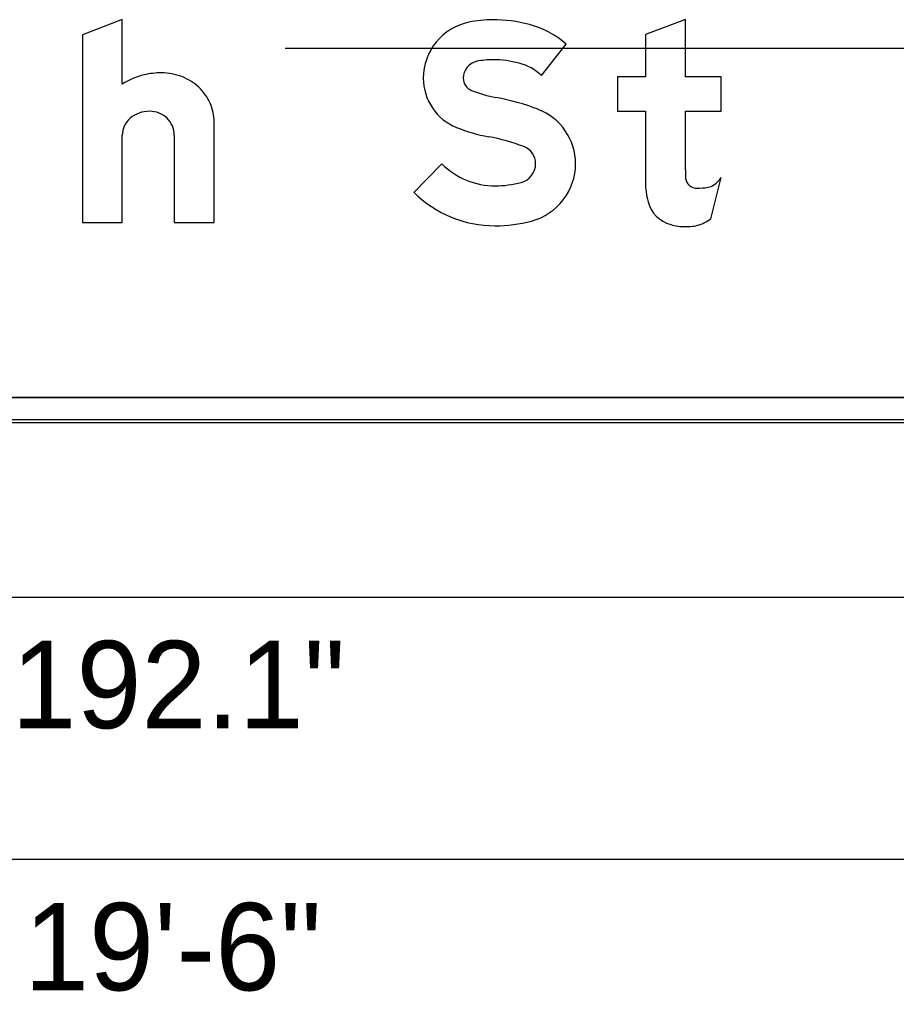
# Model space of a CAD drawing. Extents: x 2149934 to 2150188, y 145114 to 145238.
# Drawn here: x 2150097.15 to 2150103.01, y 145194.64 to 145201.13 of the extents above; entities that cross this region are included whole.
import ezdxf

# ---------------------------------------------------------------- set-up
doc = ezdxf.new("R2010")
doc.units = 0
for name, color, linetype in [('GSBWFILL', 7, 'Continuous'), ('GSCOLORFILL', 7, 'Continuous'), ('GSDIMS', 7, 'Continuous'), ('GSOUTLINE', 7, 'Continuous'), ('NON-PLOT', 7, 'Continuous')]:
    doc.layers.add(name, color=color, linetype=linetype)

msp = doc.modelspace()

# ---------------------------------------------------------------- linework, layer by layer
at = {"layer": 'GSBWFILL'}
for p, q in [((2150101.7691, 145199.8029), (2150101.8393, 145200.0789)), ((2150107.2786, 145198.6114), (2150088.7803, 145198.6114)), ((2150088.7803, 145198.4447), (2150107.2786, 145198.4447))]:
    msp.add_line(p, q, dxfattribs=at)
for points in [[(2150097.8393, 145200.7033), (2150097.8393, 145201.1347), (2150097.5726, 145201.0318), (2150097.5726, 145199.7781), (2150097.8393, 145199.7781), (2150097.8393, 145200.3629)], [(2150101.5993, 145200.1314), (2150101.5993, 145200.5214), (2150101.8393, 145200.5214), (2150101.8393, 145200.7514), (2150101.5993, 145200.7514), (2150101.5993, 145201.1347), (2150101.3326, 145201.0336), (2150101.3326, 145200.7514), (2150101.146, 145200.7514), (2150101.146, 145200.5214), (2150101.3326, 145200.5214), (2150101.3326, 145200.0508)], [(2150100.6394, 145200.7595), (2150100.8043, 145200.9699)], [(2150098.186, 145200.3629), (2150098.186, 145199.7781), (2150098.4526, 145199.7781), (2150098.4526, 145200.4506)], [(2150099.9737, 145200.1699), (2150099.786, 145199.9805)]]:
    msp.add_lwpolyline(points, dxfattribs=at)
for centre, major_axis, ratio, start_param, end_param in [((2150100.3126, 145200.347), (0, 0.7855), 0.999996, 0, 0.202758), ((2150100.3126, 145200.1692), (0, 0.9632), 0.999996, 6.026234, 6.283185), ((2150100.2313, 145200.7422), (0, 0.382), 0.999996, 0.202758, 1.570796), ((2150100.402, 145200.5094), (0, 0.6115), 0.999996, 5.565152, 6.026234), ((2150100.3126, 145200.347), (0, 0.5188), 0.999996, 0, 0.202758), ((2150100.3126, 145200.1692), (0, 0.6965), 0.999996, 6.026234, 6.283185), ((2150100.2313, 145200.7422), (0, 0.1153), 0.999996, 0.202758, 1.570796), ((2150100.402, 145200.5094), (0, 0.3448), 0.999996, 5.523837, 6.026234), ((2150098.0972, 145200.2983), (0, 0.4802), 0.999993, 0.235088, 0.567132), ((2150098.1018, 145200.2447), (0, 0.5334), 0.999993, 0, 0.219986), ((2150098.1018, 145200.4027), (0, 0.3754), 0.999993, 5.914285, 6.283185), ((2150098.1108, 145200.4261), (0, 0.3503), 0.999993, 5.532258, 5.914285), ((2150100.2032, 145200.7422), (0, 0.3538), 0.999996, 1.570796, 2.761249), ((2150100.2032, 145200.7422), (0, 0.0872), 0.999996, 1.570796, 2.761249), ((2150098.1248, 145200.441), (0, 0.3299), 0.999993, 5.130076, 5.532258), ((2150100.4938, 145201.469), (0, 0.8699), 0.999996, 2.761249, 2.95744), ((2150100.0373, 145199.018), (0, 1.6233), 0.999996, 5.918637, 6.099033), ((2150098.1465, 145200.4506), (0, 0.3062), 0.999993, 4.712389, 5.130076), ((2150097.9995, 145200.3527), (0, 0.1625), 0.999993, 0.715718, 1.126231), ((2150098.0133, 145200.3369), (0, 0.1835), 0.999993, 0.345704, 0.715718), ((2150098.0222, 145200.312), (0, 0.2099), 0.999993, 0, 0.345704), ((2150098.0222, 145200.3535), (0, 0.1684), 0.999993, 5.900624, 6.283185), ((2150098.0241, 145200.3581), (0, 0.1635), 0.999993, 5.51227, 5.900624), ((2150098.0269, 145200.361), (0, 0.1594), 0.999993, 5.115435, 5.51227), ((2150100.4775, 145200.1716), (0, 0.3885), 0.999996, 4.712389, 5.918637), ((2150097.9782, 145200.3629), (0, 0.1389), 0.999993, 1.126231, 1.570796), ((2150098.0313, 145200.3629), (0, 0.1546), 0.999993, 4.712389, 5.115435), ((2150100.4938, 145201.469), (0, 1.1366), 0.999996, 2.761249, 2.95744), ((2150100.0373, 145199.018), (0, 1.3566), 0.999996, 5.918637, 6.099033), ((2150100.4775, 145200.1716), (0, 0.1218), 0.999996, 4.712389, 5.918637), ((2150100.3288, 145200.5282), (0, 0.5044), 0.999996, 2.360607, 3.141593), ((2150100.4698, 145200.1716), (0, 0.1295), 0.999996, 3.401517, 4.712389), ((2150100.4698, 145200.1716), (0, 0.3961), 0.999996, 3.401517, 4.712389), ((2150103.2686, 145200.1314), (0, 1.6693), 0.999994, 1.570796, 1.606005), ((2150100.3288, 145200.702), (0, 0.6782), 0.999996, 3.141593, 3.401517), ((2150101.85, 145200.0508), (0, 0.5174), 0.999994, 1.570796, 1.830698), ((2150101.6759, 145200.0856), (0, 0.0767), 0.999994, 1.74085, 2.407828), ((2150101.6783, 145200.0883), (0, 0.0803), 0.999994, 2.407828, 3.141593), ((2150101.7324, 145200.1126), (0, 0.1), 0.999994, 3.310762, 3.756278), ((2150101.6638, 145200.2098), (0, 0.2189), 0.999994, 3.756278, 4.071638), ((2150100.3288, 145200.5282), (0, 0.7711), 0.999996, 2.360607, 3.141593), ((2150101.6783, 145200.4291), (0, 0.4211), 0.999994, 3.141593, 3.310762), ((2150101.5594, 145199.9735), (0, 0.2167), 0.999994, 1.830698, 2.869526), ((2150100.3288, 145200.702), (0, 0.9449), 0.999996, 3.141593, 3.401517), ((2150101.5993, 145200.1165), (0, 0.3651), 0.999994, 2.869526, 3.141593), ((2150101.6191, 145199.9687), (0, 0.2167), 0.999994, 3.205734, 3.427755), ((2150101.5907, 145200.0652), (0, 0.3172), 0.999994, 3.427755, 3.738844), ((2150101.5993, 145200.2773), (0, 0.5258), 0.999994, 3.141593, 3.205734)]:
    msp.add_ellipse(centre, major_axis=major_axis, ratio=ratio, start_param=start_param, end_param=end_param, dxfattribs=at)
at = {"layer": 'GSCOLORFILL'}
for p, q in [((2150101.7691, 145199.8029), (2150101.8393, 145200.0789)), ((2150107.2786, 145198.6114), (2150088.7803, 145198.6114)), ((2150107.2786, 145198.4614), (2150088.7788, 145198.4614)), ((2150088.7786, 145198.4447), (2150107.2786, 145198.4447)), ((2150088.7788, 145198.4447), (2150107.2786, 145198.4447)), ((2150088.7803, 145198.4447), (2150107.2786, 145198.4447))]:
    msp.add_line(p, q, dxfattribs=at)
for points in [[(2150097.8393, 145200.7033), (2150097.8393, 145201.1347), (2150097.5726, 145201.0318), (2150097.5726, 145199.7781), (2150097.8393, 145199.7781), (2150097.8393, 145200.3629)], [(2150101.5993, 145200.1314), (2150101.5993, 145200.5214), (2150101.8393, 145200.5214), (2150101.8393, 145200.7514), (2150101.5993, 145200.7514), (2150101.5993, 145201.1347), (2150101.3326, 145201.0336), (2150101.3326, 145200.7514), (2150101.146, 145200.7514), (2150101.146, 145200.5214), (2150101.3326, 145200.5214), (2150101.3326, 145200.0508)], [(2150100.6394, 145200.7595), (2150100.8043, 145200.9699)], [(2150098.186, 145200.3629), (2150098.186, 145199.7781), (2150098.4526, 145199.7781), (2150098.4526, 145200.4506)], [(2150099.9737, 145200.1699), (2150099.786, 145199.9805)]]:
    msp.add_lwpolyline(points, dxfattribs=at)
for centre, major_axis, ratio, start_param, end_param in [((2150100.3126, 145200.347), (0, 0.7855), 0.999996, 0, 0.202758), ((2150100.3126, 145200.1692), (0, 0.9632), 0.999996, 6.026234, 6.283185), ((2150100.2313, 145200.7422), (0, 0.382), 0.999996, 0.202758, 1.570796), ((2150100.402, 145200.5094), (0, 0.6115), 0.999996, 5.565152, 6.026234), ((2150100.3126, 145200.347), (0, 0.5188), 0.999996, 0, 0.202758), ((2150100.3126, 145200.1692), (0, 0.6965), 0.999996, 6.026234, 6.283185), ((2150100.2313, 145200.7422), (0, 0.1153), 0.999996, 0.202758, 1.570796), ((2150100.402, 145200.5094), (0, 0.3448), 0.999996, 5.523837, 6.026234), ((2150098.0972, 145200.2983), (0, 0.4802), 0.999993, 0.235088, 0.567132), ((2150098.1018, 145200.2447), (0, 0.5334), 0.999993, 0, 0.219986), ((2150098.1018, 145200.4027), (0, 0.3754), 0.999993, 5.914285, 6.283185), ((2150098.1108, 145200.4261), (0, 0.3503), 0.999993, 5.532258, 5.914285), ((2150100.2032, 145200.7422), (0, 0.3538), 0.999996, 1.570796, 2.761249), ((2150100.2032, 145200.7422), (0, 0.0872), 0.999996, 1.570796, 2.761249), ((2150098.1248, 145200.441), (0, 0.3299), 0.999993, 5.130076, 5.532258), ((2150100.4938, 145201.469), (0, 0.8699), 0.999996, 2.761249, 2.95744), ((2150100.0373, 145199.018), (0, 1.6233), 0.999996, 5.918637, 6.099033), ((2150098.1465, 145200.4506), (0, 0.3062), 0.999993, 4.712389, 5.130076), ((2150097.9995, 145200.3527), (0, 0.1625), 0.999993, 0.715718, 1.126231), ((2150098.0133, 145200.3369), (0, 0.1835), 0.999993, 0.345704, 0.715718), ((2150098.0222, 145200.312), (0, 0.2099), 0.999993, 0, 0.345704), ((2150098.0222, 145200.3535), (0, 0.1684), 0.999993, 5.900624, 6.283185), ((2150098.0241, 145200.3581), (0, 0.1635), 0.999993, 5.51227, 5.900624), ((2150098.0269, 145200.361), (0, 0.1594), 0.999993, 5.115435, 5.51227), ((2150100.4775, 145200.1716), (0, 0.3885), 0.999996, 4.712389, 5.918637), ((2150097.9782, 145200.3629), (0, 0.1389), 0.999993, 1.126231, 1.570796), ((2150098.0313, 145200.3629), (0, 0.1546), 0.999993, 4.712389, 5.115435), ((2150100.4938, 145201.469), (0, 1.1366), 0.999996, 2.761249, 2.95744), ((2150100.0373, 145199.018), (0, 1.3566), 0.999996, 5.918637, 6.099033), ((2150100.4775, 145200.1716), (0, 0.1218), 0.999996, 4.712389, 5.918637), ((2150100.3288, 145200.5282), (0, 0.5044), 0.999996, 2.360607, 3.141593), ((2150100.4698, 145200.1716), (0, 0.1295), 0.999996, 3.401517, 4.712389), ((2150100.4698, 145200.1716), (0, 0.3961), 0.999996, 3.401517, 4.712389), ((2150103.2686, 145200.1314), (0, 1.6693), 0.999994, 1.570796, 1.606005), ((2150100.3288, 145200.702), (0, 0.6782), 0.999996, 3.141593, 3.401517), ((2150101.85, 145200.0508), (0, 0.5174), 0.999994, 1.570796, 1.830698), ((2150101.6759, 145200.0856), (0, 0.0767), 0.999994, 1.74085, 2.407828), ((2150101.6783, 145200.0883), (0, 0.0803), 0.999994, 2.407828, 3.141593), ((2150101.7324, 145200.1126), (0, 0.1), 0.999994, 3.310762, 3.756278), ((2150101.6638, 145200.2098), (0, 0.2189), 0.999994, 3.756278, 4.071638), ((2150100.3288, 145200.5282), (0, 0.7711), 0.999996, 2.360607, 3.141593), ((2150101.6783, 145200.4291), (0, 0.4211), 0.999994, 3.141593, 3.310762), ((2150101.5594, 145199.9735), (0, 0.2167), 0.999994, 1.830698, 2.869526), ((2150100.3288, 145200.702), (0, 0.9449), 0.999996, 3.141593, 3.401517), ((2150101.5993, 145200.1165), (0, 0.3651), 0.999994, 2.869526, 3.141593), ((2150101.6191, 145199.9687), (0, 0.2167), 0.999994, 3.205734, 3.427755), ((2150101.5907, 145200.0652), (0, 0.3172), 0.999994, 3.427755, 3.738844), ((2150101.5993, 145200.2773), (0, 0.5258), 0.999994, 3.141593, 3.205734)]:
    msp.add_ellipse(centre, major_axis=major_axis, ratio=ratio, start_param=start_param, end_param=end_param, dxfattribs=at)
at = {"layer": 'GSDIMS'}
for p, q in [((2150090.026, 145197.278), (2150106.0313, 145197.278)), ((2150088.2786, 145195.528), (2150107.7787, 145195.528))]:
    msp.add_line(p, q, dxfattribs=at)
at = {"layer": 'GSOUTLINE'}
for p, q in [((2150101.7691, 145199.8029), (2150101.8393, 145200.0789)), ((2150088.7786, 145198.6114), (2150107.2786, 145198.6114)), ((2150088.7786, 145198.4447), (2150107.2786, 145198.4447))]:
    msp.add_line(p, q, dxfattribs=at)
for points in [[(2150097.8393, 145200.7033), (2150097.8393, 145201.1347), (2150097.5726, 145201.0318), (2150097.5726, 145199.7781), (2150097.8393, 145199.7781), (2150097.8393, 145200.3629)], [(2150101.5993, 145200.1314), (2150101.5993, 145200.5214), (2150101.8393, 145200.5214), (2150101.8393, 145200.7514), (2150101.5993, 145200.7514), (2150101.5993, 145201.1347), (2150101.3326, 145201.0336), (2150101.3326, 145200.7514), (2150101.146, 145200.7514), (2150101.146, 145200.5214), (2150101.3326, 145200.5214), (2150101.3326, 145200.0508)], [(2150100.6394, 145200.7595), (2150100.8043, 145200.9699)], [(2150098.186, 145200.3629), (2150098.186, 145199.7781), (2150098.4526, 145199.7781), (2150098.4526, 145200.4506)], [(2150099.9737, 145200.1699), (2150099.786, 145199.9805)]]:
    msp.add_lwpolyline(points, dxfattribs=at)
for centre, major_axis, ratio, start_param, end_param in [((2150100.3126, 145200.347), (0, 0.7855), 0.999996, 0, 0.202758), ((2150100.3126, 145200.1692), (0, 0.9632), 0.999996, 6.026234, 6.283185), ((2150100.2313, 145200.7422), (0, 0.382), 0.999996, 0.202758, 1.570796), ((2150100.402, 145200.5094), (0, 0.6115), 0.999996, 5.565152, 6.026234), ((2150100.3126, 145200.347), (0, 0.5188), 0.999996, 0, 0.202758), ((2150100.3126, 145200.1692), (0, 0.6965), 0.999996, 6.026234, 6.283185), ((2150100.2313, 145200.7422), (0, 0.1153), 0.999996, 0.202758, 1.570796), ((2150100.402, 145200.5094), (0, 0.3448), 0.999996, 5.523837, 6.026234), ((2150098.0972, 145200.2983), (0, 0.4802), 0.999993, 0.235088, 0.567132), ((2150098.1018, 145200.2447), (0, 0.5334), 0.999993, 0, 0.219986), ((2150098.1018, 145200.4027), (0, 0.3754), 0.999993, 5.914285, 6.283185), ((2150098.1108, 145200.4261), (0, 0.3503), 0.999993, 5.532258, 5.914285), ((2150100.2032, 145200.7422), (0, 0.3538), 0.999996, 1.570796, 2.761249), ((2150100.2032, 145200.7422), (0, 0.0872), 0.999996, 1.570796, 2.761249), ((2150098.1248, 145200.441), (0, 0.3299), 0.999993, 5.130076, 5.532258), ((2150100.4938, 145201.469), (0, 0.8699), 0.999996, 2.761249, 2.95744), ((2150100.0373, 145199.018), (0, 1.6233), 0.999996, 5.918637, 6.099033), ((2150098.1465, 145200.4506), (0, 0.3062), 0.999993, 4.712389, 5.130076), ((2150097.9995, 145200.3527), (0, 0.1625), 0.999993, 0.715718, 1.126231), ((2150098.0133, 145200.3369), (0, 0.1835), 0.999993, 0.345704, 0.715718), ((2150098.0222, 145200.312), (0, 0.2099), 0.999993, 0, 0.345704), ((2150098.0222, 145200.3535), (0, 0.1684), 0.999993, 5.900624, 6.283185), ((2150098.0241, 145200.3581), (0, 0.1635), 0.999993, 5.51227, 5.900624), ((2150098.0269, 145200.361), (0, 0.1594), 0.999993, 5.115435, 5.51227), ((2150100.4775, 145200.1716), (0, 0.3885), 0.999996, 4.712389, 5.918637), ((2150097.9782, 145200.3629), (0, 0.1389), 0.999993, 1.126231, 1.570796), ((2150098.0313, 145200.3629), (0, 0.1546), 0.999993, 4.712389, 5.115435), ((2150100.4938, 145201.469), (0, 1.1366), 0.999996, 2.761249, 2.95744), ((2150100.0373, 145199.018), (0, 1.3566), 0.999996, 5.918637, 6.099033), ((2150100.4775, 145200.1716), (0, 0.1218), 0.999996, 4.712389, 5.918637), ((2150100.3288, 145200.5282), (0, 0.5044), 0.999996, 2.360607, 3.141593), ((2150100.4698, 145200.1716), (0, 0.1295), 0.999996, 3.401517, 4.712389), ((2150100.4698, 145200.1716), (0, 0.3961), 0.999996, 3.401517, 4.712389), ((2150103.2686, 145200.1314), (0, 1.6693), 0.999994, 1.570796, 1.606005), ((2150100.3288, 145200.702), (0, 0.6782), 0.999996, 3.141593, 3.401517), ((2150101.85, 145200.0508), (0, 0.5174), 0.999994, 1.570796, 1.830698), ((2150101.6759, 145200.0856), (0, 0.0767), 0.999994, 1.74085, 2.407828), ((2150101.6783, 145200.0883), (0, 0.0803), 0.999994, 2.407828, 3.141593), ((2150101.7324, 145200.1126), (0, 0.1), 0.999994, 3.310762, 3.756278), ((2150101.6638, 145200.2098), (0, 0.2189), 0.999994, 3.756278, 4.071638), ((2150100.3288, 145200.5282), (0, 0.7711), 0.999996, 2.360607, 3.141593), ((2150101.6783, 145200.4291), (0, 0.4211), 0.999994, 3.141593, 3.310762), ((2150101.5594, 145199.9735), (0, 0.2167), 0.999994, 1.830698, 2.869526), ((2150100.3288, 145200.702), (0, 0.9449), 0.999996, 3.141593, 3.401517), ((2150101.5993, 145200.1165), (0, 0.3651), 0.999994, 2.869526, 3.141593), ((2150101.6191, 145199.9687), (0, 0.2167), 0.999994, 3.205734, 3.427755), ((2150101.5907, 145200.0652), (0, 0.3172), 0.999994, 3.427755, 3.738844), ((2150101.5993, 145200.2773), (0, 0.5258), 0.999994, 3.141593, 3.205734)]:
    msp.add_ellipse(centre, major_axis=major_axis, ratio=ratio, start_param=start_param, end_param=end_param, dxfattribs=at)
at = {"layer": 'NON-PLOT'}
for p, q in [((2150098.9272, 145200.9421), (2150104.9589, 145200.9421)), ((2150098.0286, 145200.4447), (2150098.0286, 145200.4447)), ((2150098.0287, 145200.4447), (2150098.0287, 145200.4447))]:
    msp.add_line(p, q, dxfattribs=at)

# ---------------------------------------------------------------- texts
at = {"layer": 'GSDIMS'}
for s, p in [('192.1"', (2150097.0997, 145196.403)), ('19\'-6"', (2150097.1835, 145194.653))]:
    msp.add_text(s, height=0.58333, dxfattribs=at).set_placement(p)

doc.saveas('drawing.dxf')
